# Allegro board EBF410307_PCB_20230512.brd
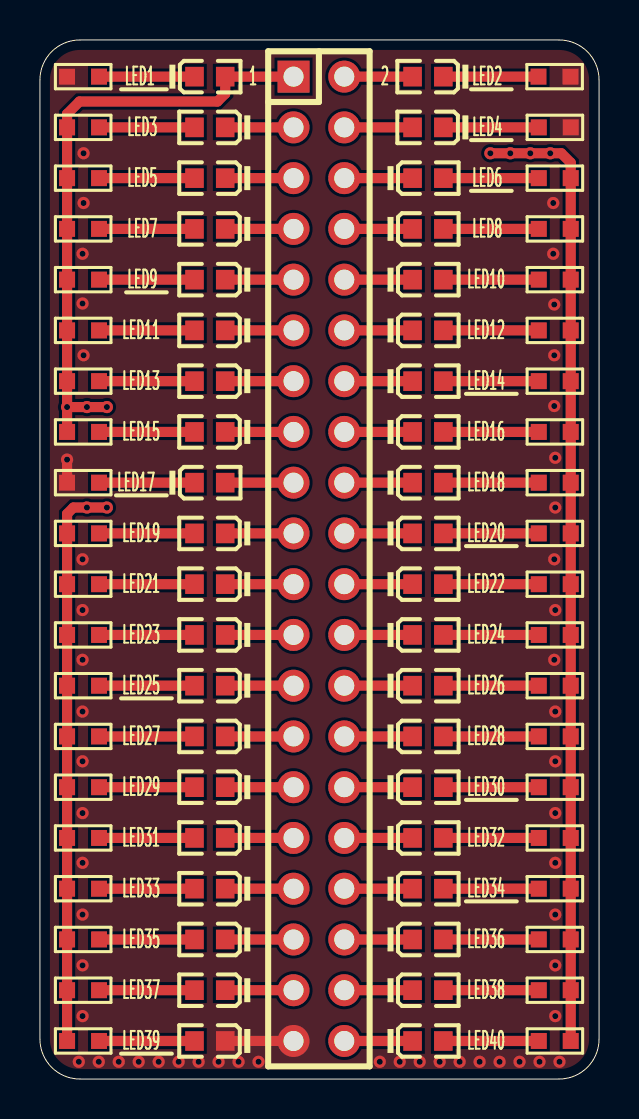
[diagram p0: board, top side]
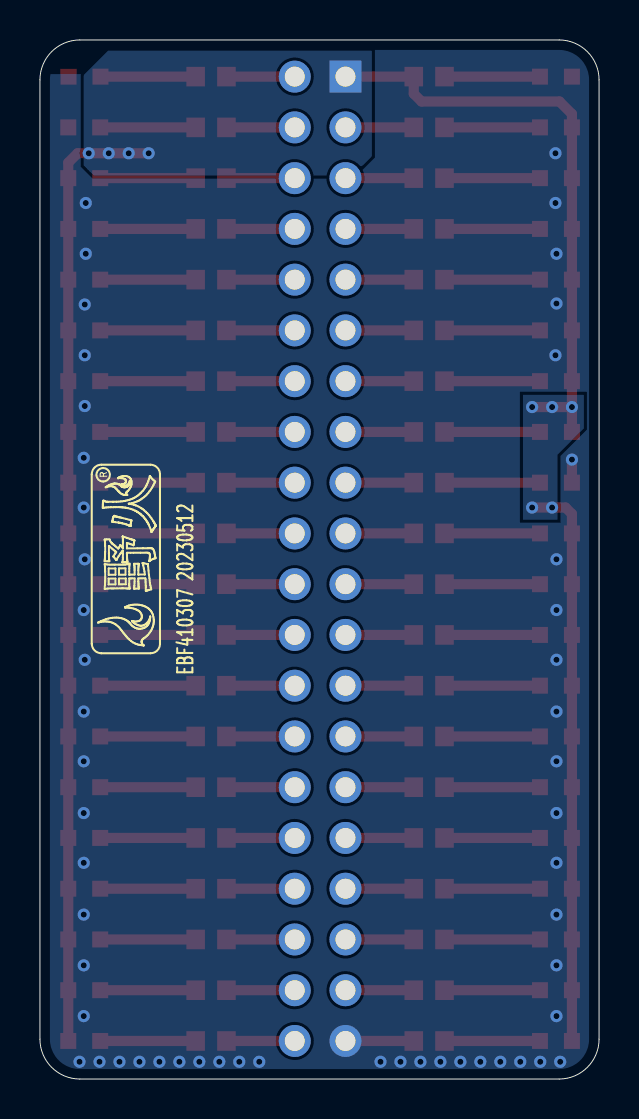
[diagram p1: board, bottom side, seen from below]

Outline 28 x 52 mm; copper layers: TOP, BOTTOM. Coordinates in mm from the lower left corner of the outline.
Outline path: 0,50 0,2 arc(0.59,0.59) 2,0 26,0 arc(27.41,0.59) 28,2 28,50 arc(27.41,51.41) 26,52 2,52 arc(0.59,51.41) 0,50

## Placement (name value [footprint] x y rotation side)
J1  2X20PIN-F  [DIP-2X20_2P54]  13.97 26.04 270 top
LED1  GREEN  [LED0603]  8.51 50.16 180 top
LED2  GREEN  [LED0603]  19.43 50.16 0 top
LED3  GREEN  [LED0603]  8.51 47.62 0 top
LED4  GREEN  [LED0603]  19.43 47.62 0 top
LED5  GREEN  [LED0603]  8.51 45.09 0 top
LED6  GREEN  [LED0603]  19.43 45.09 180 top
LED7  GREEN  [LED0603]  8.51 42.55 0 top
LED8  GREEN  [LED0603]  19.43 42.55 180 top
LED9  GREEN  [LED0603]  8.51 40.01 0 top
LED10  GREEN  [LED0603]  19.43 40.01 180 top
LED11  GREEN  [LED0603]  8.51 37.47 0 top
LED12  GREEN  [LED0603]  19.43 37.47 180 top
LED13  GREEN  [LED0603]  8.51 34.92 0 top
LED14  GREEN  [LED0603]  19.43 34.92 180 top
LED15  GREEN  [LED0603]  8.51 32.38 0 top
LED16  GREEN  [LED0603]  19.43 32.38 180 top
LED17  GREEN  [LED0603]  8.51 29.84 180 top
LED18  GREEN  [LED0603]  19.43 29.84 180 top
LED19  GREEN  [LED0603]  8.51 27.3 0 top
LED20  GREEN  [LED0603]  19.43 27.3 180 top
LED21  GREEN  [LED0603]  8.51 24.77 0 top
LED22  GREEN  [LED0603]  19.43 24.77 180 top
LED23  GREEN  [LED0603]  8.51 22.23 0 top
LED24  GREEN  [LED0603]  19.43 22.23 180 top
LED25  GREEN  [LED0603]  8.51 19.68 0 top
LED26  GREEN  [LED0603]  19.43 19.68 180 top
LED27  GREEN  [LED0603]  8.51 17.14 0 top
LED28  GREEN  [LED0603]  19.43 17.14 180 top
LED29  GREEN  [LED0603]  8.51 14.61 0 top
LED30  GREEN  [LED0603]  19.43 14.61 180 top
LED31  GREEN  [LED0603]  8.51 12.06 0 top
LED32  GREEN  [LED0603]  19.43 12.06 180 top
LED33  GREEN  [LED0603]  8.51 9.53 0 top
LED34  GREEN  [LED0603]  19.43 9.53 180 top
LED35  GREEN  [LED0603]  8.51 6.99 0 top
LED36  GREEN  [LED0603]  19.43 6.99 180 top
LED37  GREEN  [LED0603]  8.51 4.45 0 top
LED38  GREEN  [LED0603]  19.43 4.45 180 top
LED39  GREEN  [LED0603]  8.51 1.91 0 top
LED40  GREEN  [LED0603]  19.43 1.91 180 top
R1  4.7K  [R0603]  2.16 50.16 0 top
R2  4.7K  [R0603]  25.77 50.16 0 top
R3  4.7K  [R0603]  2.16 47.62 0 top
R4  4.7K  [R0603]  25.78 47.62 0 top
R5  4.7K  [R0603]  2.16 45.09 0 top
R6  4.7K  [R0603]  25.78 45.09 0 top
R7  4.7K  [R0603]  2.16 42.55 0 top
R8  4.7K  [R0603]  25.78 42.55 0 top
R9  4.7K  [R0603]  2.16 40.01 0 top
R10  4.7K  [R0603]  25.78 40.01 0 top
R11  4.7K  [R0603]  2.16 37.47 0 top
R12  4.7K  [R0603]  25.78 37.47 0 top
R13  4.7K  [R0603]  2.16 34.92 0 top
R14  4.7K  [R0603]  25.78 34.92 0 top
R15  4.7K  [R0603]  2.16 32.38 0 top
R16  4.7K  [R0603]  25.78 32.38 0 top
R17  4.7K  [R0603]  2.16 29.84 0 top
R18  4.7K  [R0603]  25.78 29.84 0 top
R19  4.7K  [R0603]  2.16 27.3 0 top
R20  4.7K  [R0603]  25.78 27.3 0 top
R21  4.7K  [R0603]  2.16 24.77 0 top
R22  4.7K  [R0603]  25.78 24.77 0 top
R23  4.7K  [R0603]  2.16 22.23 0 top
R24  4.7K  [R0603]  25.78 22.23 0 top
R25  4.7K  [R0603]  2.16 19.68 0 top
R26  4.7K  [R0603]  25.78 19.68 0 top
R27  4.7K  [R0603]  2.16 17.14 0 top
R28  4.7K  [R0603]  25.78 17.14 0 top
R29  4.7K  [R0603]  2.16 14.61 0 top
R30  4.7K  [R0603]  25.78 14.61 0 top
R31  4.7K  [R0603]  2.16 12.06 0 top
R32  4.7K  [R0603]  25.78 12.06 0 top
R33  4.7K  [R0603]  2.16 9.53 0 top
R34  4.7K  [R0603]  25.78 9.53 0 top
R35  4.7K  [R0603]  2.16 6.99 0 top
R36  4.7K  [R0603]  25.78 6.99 0 top
R37  4.7K  [R0603]  2.16 4.45 0 top
R38  4.7K  [R0603]  25.78 4.45 0 top
R39  4.7K  [R0603]  2.16 1.91 0 top
R40  4.7K  [R0603]  25.78 1.91 0 top

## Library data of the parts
J1 = 2X20PIN
LED1-LED40 = LED
R1-R40 = RES

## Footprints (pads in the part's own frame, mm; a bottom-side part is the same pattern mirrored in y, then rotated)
DIP-2X20_2P54
  rect 1.6x1.6 hole 1: 1(-24.13,-1.27)
  round 1.6 hole 1: 2(-24.13,1.27) 3(-21.59,-1.27) 4(-21.59,1.27) 5(-19.05,-1.27) 6(-19.05,1.27) 7(-16.51,-1.27) 8(-16.51,1.27) 9(-13.97,-1.27) 10(-13.97,1.27) 11(-11.43,-1.27) 12(-11.43,1.27) 13(-8.89,-1.27) 14(-8.89,1.27) 15(-6.35,-1.27) 16(-6.35,1.27) 17(-3.81,-1.27) 18(-3.81,1.27) 19(-1.27,-1.27) 20(-1.27,1.27) 21(1.27,-1.27) 22(1.27,1.27) 23(3.81,-1.27) 24(3.81,1.27) 25(6.35,-1.27) 26(6.35,1.27) 27(8.89,-1.27) 28(8.89,1.27) 29(11.43,-1.27) 30(11.43,1.27) 31(13.97,-1.27) 32(13.97,1.27) 33(16.51,-1.27) 34(16.51,1.27) 35(19.05,-1.27) 36(19.05,1.27) 37(21.59,-1.27) 38(21.59,1.27) 39(24.13,-1.27) 40(24.13,1.27)
LED0603
  rect 0.93x0.98 smd: 1(0.77,0) 2(-0.77,0)
R0603
  rect 0.8x0.8 smd: 1(-0.8,0) 2(0.8,0)

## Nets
GND: J1.39 LED39.1(CATHODE) R1.1 R2.2 R4.2 R17.1
VCC_3V3: J1.1 LED1.2(ANODE) R3.1 R5.1 R6.2 R7.1 R8.2 R9.1 R10.2 R11.1 R12.2 R13.1 R14.2 R15.1 R16.2 R18.2 R19.1 R20.2 R21.1 R22.2 R23.1 R24.2 R25.1 R26.2 R27.1 R28.2 R29.1 R30.2 R31.1 R32.2 R33.1 R34.2 R35.1 R36.2 R37.1 R38.2 R39.1 R40.2
N16483237: J1.2 LED2.2(ANODE)
N16483392: LED2.1(CATHODE) R2.1
N16483434: J1.3 LED3.1(CATHODE)
N16483438: LED3.2(ANODE) R3.2
N16483442: LED1.1(CATHODE) R1.2
N16483540: J1.4 LED4.2(ANODE)
N16483576: LED4.1(CATHODE) R4.1
N16484980: J1.5 LED5.1(CATHODE)
N16484992: J1.7 LED7.1(CATHODE)
N16485004: J1.9 LED9.1(CATHODE)
N16485016: J1.11 LED11.1(CATHODE)
N16485028: J1.13 LED13.1(CATHODE)
N16485040: J1.15 LED15.1(CATHODE)
N16485229: J1.17 LED17.2(ANODE)
N16485267: J1.19 LED19.1(CATHODE)
N16485335: J1.21 LED21.1(CATHODE)
N16485347: J1.23 LED23.1(CATHODE)
N16485387: J1.27 LED27.1(CATHODE)
N16485391: J1.29 LED29.1(CATHODE)
N16485403: J1.31 LED31.1(CATHODE)
N16485415: J1.33 LED33.1(CATHODE)
N16485427: J1.35 LED35.1(CATHODE)
N16485439: J1.37 LED37.1(CATHODE)
N16485492: J1.6 LED6.1(CATHODE)
N16485496: J1.8 LED8.1(CATHODE)
N16485534: J1.25 LED25.1(CATHODE)
N16485584: J1.10 LED10.1(CATHODE)
N16485596: J1.12 LED12.1(CATHODE)
N16485608: J1.14 LED14.1(CATHODE)
N16485620: J1.16 LED16.1(CATHODE)
N16485632: J1.18 LED18.1(CATHODE)
N16485644: J1.20 LED20.1(CATHODE)
N16485656: J1.22 LED22.1(CATHODE)
N16485668: J1.24 LED24.1(CATHODE)
N16485680: J1.26 LED26.1(CATHODE)
N16485692: J1.28 LED28.1(CATHODE)
N16485704: J1.30 LED30.1(CATHODE)
N16485716: J1.32 LED32.1(CATHODE)
N16485728: J1.34 LED34.1(CATHODE)
N16485740: J1.36 LED36.1(CATHODE)
N16485752: J1.38 LED38.1(CATHODE)
N16485764: J1.40 LED40.1(CATHODE)
N16551066: LED5.2(ANODE) R5.2
N16551078: LED7.2(ANODE) R7.2
N16551090: LED9.2(ANODE) R9.2
N16551102: LED11.2(ANODE) R11.2
N16551114: LED13.2(ANODE) R13.2
N16551126: LED15.2(ANODE) R15.2
N16551138: LED17.1(CATHODE) R17.2
N16551155: LED19.2(ANODE) R19.2
N16551167: LED21.2(ANODE) R21.2
N16551179: LED23.2(ANODE) R23.2
N16551191: LED25.2(ANODE) R25.2
N16551203: LED27.2(ANODE) R27.2
N16551215: LED29.2(ANODE) R29.2
N16551227: LED31.2(ANODE) R31.2
N16551239: LED33.2(ANODE) R33.2
N16551251: LED35.2(ANODE) R35.2
N16551263: LED37.2(ANODE) R37.2
N16551275: LED39.2(ANODE) R39.2
N16551283: LED6.2(ANODE) R6.1
N16551295: LED8.2(ANODE) R8.1
N16551307: LED10.2(ANODE) R10.1
N16551319: LED12.2(ANODE) R12.1
N16551331: LED14.2(ANODE) R14.1
N16551343: LED16.2(ANODE) R16.1
N16551355: LED18.2(ANODE) R18.1
N16551367: LED20.2(ANODE) R20.1
N16551379: LED22.2(ANODE) R22.1
N16551391: LED24.2(ANODE) R24.1
N16551403: LED26.2(ANODE) R26.1
N16551415: LED28.2(ANODE) R28.1
N16551427: LED30.2(ANODE) R30.1
N16551439: LED32.2(ANODE) R32.1
N16551451: LED34.2(ANODE) R34.1
N16551463: LED36.2(ANODE) R36.1
N16551475: LED38.2(ANODE) R38.1
N16551487: LED40.2(ANODE) R40.1

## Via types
v1: diameter 0.61, hole 0.305, TOP to BOTTOM, 62 vias

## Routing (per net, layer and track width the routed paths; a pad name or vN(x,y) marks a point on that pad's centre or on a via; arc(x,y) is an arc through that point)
GND: length 4.6
  TOP w0.508: R17.1 v1(1.36,31) ; 12.7,1.91 LED39.1
  vias: v1(1.95,0.86) v1(2.13,41.3) v1(2.13,38.81) v1(2.13,26.01) v1(2.13,23.47) v1(2.13,20.98) v1(2.13,18.39) v1(2.13,15.9) v1(2.13,13.31) v1(2.13,10.82) v1(2.13,8.23) v1(2.13,5.69) v1(2.13,3.15) v1(2.18,46.33) v1(2.18,43.84) v1(2.18,36.22) v1(2.95,0.86) v1(3.95,0.86) v1(4.95,0.86) v1(5.95,0.86) v1(6.95,0.86) v1(7.95,0.86) v1(8.95,0.86) v1(9.95,0.86) v1(10.95,0.86) v1(17.02,0.86) v1(18.02,0.86) v1(19.02,0.86) v1(20.02,0.86) v1(21.02,0.86) v1(22.02,0.86) v1(23.02,0.86) v1(24.02,0.86) v1(25.02,0.86) v1(25.7,43.84) v1(25.7,41.3) v1(25.76,38.76) v1(25.76,36.22) v1(25.76,33.68) v1(25.81,31.09) v1(25.81,28.6) v1(25.76,26.01) v1(25.81,23.47) v1(25.76,20.98) v1(25.81,18.39) v1(25.81,15.9) v1(25.81,13.31) v1(25.81,10.82) v1(25.81,8.23) v1(25.81,5.69) v1(25.81,3.15) v1(26.02,0.86)
VCC_3V3: length 107.2
  TOP w0.508: v1(1.36,33.63) R13.1 R11.1 R9.1 R7.1 R5.1 R3.1 1.36,48.3 1.98,48.92 8.89,48.92 9.28,49.31 LED1.2 J1.1 ; v1(1.36,33.63) v1(2.35,33.63) v1(3.35,33.63) ; v1(1.36,33.63) R15.1 ; R39.1 R37.1 R35.1 R33.1 R31.1 R29.1 R27.1 R25.1 R23.1 R21.1 R19.1 1.36,28.28 1.68,28.6 v1(2.35,28.6) v1(3.35,28.6) ; v1(22.56,46.33) v1(23.56,46.33) v1(24.56,46.33) v1(25.56,46.33) 26.11,46.33 26.58,45.86 R6.2 R8.2 R10.2 R12.2 R14.2 R16.2 R18.2 R20.2 R22.2 R24.2 R26.2 R28.2 R30.2 R32.2 R34.2 R36.2 R38.2 R40.2
N16483237: length 3.4
  TOP w0.508: J1.2 LED2.2
N16483392: length 4.8
  TOP w0.508: LED2.1 R2.1
N16483434: length 3.4
  TOP w0.508: J1.3 LED3.1
N16483438: length 4.8
  TOP w0.508: R3.2 LED3.2
N16483442: length 4.8
  TOP w0.508: LED1.1 R1.2
N16483540: length 3.4
  TOP w0.508: J1.4 LED4.2
N16483576: length 4.8
  TOP w0.508: LED4.1 R4.1
N16484980: length 3.4
  TOP w0.508: J1.5 LED5.1
N16484992: length 3.4
  TOP w0.508: J1.7 LED7.1
N16485004: length 3.4
  TOP w0.508: LED9.1 J1.9
N16485016: length 3.4
  TOP w0.508: LED11.1 J1.11
N16485028: length 3.4
  TOP w0.508: J1.13 LED13.1
N16485040: length 3.4
  TOP w0.508: J1.15 LED15.1
N16485229: length 3.4
  TOP w0.508: J1.17 LED17.2
N16485267: length 3.4
  TOP w0.508: J1.19 LED19.1
N16485335: length 3.4
  TOP w0.508: J1.21 LED21.1
N16485347: length 3.4
  TOP w0.508: J1.23 LED23.1
N16485387: length 3.4
  TOP w0.508: J1.27 LED27.1
N16485391: length 3.4
  TOP w0.508: J1.29 LED29.1
N16485403: length 3.4
  TOP w0.508: J1.31 LED31.1
N16485415: length 3.4
  TOP w0.508: J1.33 LED33.1
N16485427: length 3.4
  TOP w0.508: J1.35 LED35.1
N16485439: length 3.4
  TOP w0.508: J1.37 LED37.1
N16485492: length 3.4
  TOP w0.508: J1.6 LED6.1
N16485496: length 3.4
  TOP w0.508: J1.8 LED8.1
N16485534: length 3.4
  TOP w0.508: 12.7,19.68 LED25.1
N16485584: length 3.4
  TOP w0.508: J1.10 LED10.1
N16485596: length 3.4
  TOP w0.508: J1.12 LED12.1
N16485608: length 3.4
  TOP w0.508: J1.14 LED14.1
N16485620: length 3.4
  TOP w0.508: J1.16 LED16.1
N16485632: length 3.4
  TOP w0.508: J1.18 LED18.1
N16485644: length 3.4
  TOP w0.508: J1.20 LED20.1
N16485656: length 3.4
  TOP w0.508: J1.22 LED22.1
N16485668: length 3.4
  TOP w0.508: J1.24 LED24.1
N16485680: length 3.4
  TOP w0.508: 15.24,19.68 LED26.1
N16485692: length 3.4
  TOP w0.508: J1.28 LED28.1
N16485704: length 3.4
  TOP w0.508: J1.30 LED30.1
N16485716: length 3.4
  TOP w0.508: J1.32 LED32.1
N16485728: length 3.4
  TOP w0.508: J1.34 LED34.1
N16485740: length 3.4
  TOP w0.508: J1.36 LED36.1
N16485752: length 3.4
  TOP w0.508: J1.38 LED38.1
N16485764: length 3.4
  TOP w0.508: 15.24,1.91 LED40.1
N16551066: length 4.8
  TOP w0.508: LED5.2 R5.2
N16551078: length 4.8
  TOP w0.508: LED7.2 R7.2
N16551090: length 4.8
  TOP w0.508: R9.2 LED9.2
N16551102: length 4.8
  TOP w0.508: R11.2 LED11.2
N16551114: length 4.8
  TOP w0.508: R13.2 LED13.2
N16551126: length 4.8
  TOP w0.508: LED15.2 R15.2
N16551138: length 4.8
  TOP w0.508: LED17.1 R17.2
N16551155: length 4.8
  TOP w0.508: LED19.2 R19.2
N16551167: length 4.8
  TOP w0.508: LED21.2 R21.2
N16551179: length 4.8
  TOP w0.508: LED23.2 R23.2
N16551191: length 4.8
  TOP w0.508: LED25.2 R25.2
N16551203: length 4.8
  TOP w0.508: LED27.2 R27.2
N16551215: length 4.8
  TOP w0.508: LED29.2 R29.2
N16551227: length 4.8
  TOP w0.508: LED31.2 R31.2
N16551239: length 4.8
  TOP w0.508: LED33.2 R33.2
N16551251: length 4.8
  TOP w0.508: LED35.2 R35.2
N16551263: length 4.8
  TOP w0.508: LED37.2 R37.2
N16551275: length 4.8
  TOP w0.508: LED39.2 R39.2
N16551283: length 4.8
  TOP w0.508: LED6.2 R6.1
N16551295: length 4.8
  TOP w0.508: LED8.2 R8.1
N16551307: length 4.8
  TOP w0.508: LED10.2 R10.1
N16551319: length 4.8
  TOP w0.508: LED12.2 R12.1
N16551331: length 4.8
  TOP w0.508: LED14.2 R14.1
N16551343: length 4.8
  TOP w0.508: LED16.2 R16.1
N16551355: length 4.8
  TOP w0.508: LED18.2 R18.1
N16551367: length 4.8
  TOP w0.508: LED20.2 R20.1
N16551379: length 4.8
  TOP w0.508: LED22.2 R22.1
N16551391: length 4.8
  TOP w0.508: LED24.2 R24.1
N16551403: length 4.8
  TOP w0.508: LED26.2 R26.1
N16551415: length 4.8
  TOP w0.508: LED28.2 R28.1
N16551427: length 4.8
  TOP w0.508: LED30.2 R30.1
N16551439: length 4.8
  TOP w0.508: LED32.2 R32.1
N16551451: length 4.8
  TOP w0.508: LED34.2 R34.1
N16551463: length 4.8
  TOP w0.508: LED36.2 R36.1
N16551475: length 4.8
  TOP w0.508: LED38.2 R38.1
N16551487: length 4.8
  TOP w0.508: LED40.2 R40.1

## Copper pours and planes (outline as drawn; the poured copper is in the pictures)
GND on TOP: 27.5,2 27.06,0.94 26,0.5 2,0.5 0.94,0.94 0.5,2 0.5,50 0.94,51.06 2,51.5 26,51.5 27.06,51.06 27.5,50
VCC_3V3 on BOTTOM: 11.38,51.46 24.59,51.46 25.81,50.24 25.81,45.72 25.3,45.21 12.34,45.21 11.38,46.18
VCC_3V3 on BOTTOM: 0.76,34.24 0.76,32.56 2.08,31.24 2.08,27.99 3.81,27.99 3.81,34.24

Small or netless copper shapes (teardrops, artwork), in the pictures only: 1 on BOTTOM

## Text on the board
Ref Des/Silkscreen Bottom: EBF410307 20230512
Ref Des/Silkscreen Top: 1 | 2
User.8: FIGURE | SIZE | 12.0 | 39.37 | DRILL CHART: TOP to BOTTOM | ALL UNITS ARE IN MILS | PLATED | QTY | 62 | 39 | 1
